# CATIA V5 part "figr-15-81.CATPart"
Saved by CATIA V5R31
Part number: Part1
Bounding box of the stored display mesh (mm): x -28.659 to 28.659, y -52 to 52, z 0 to 2
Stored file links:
  D:\PROJECTS\Project 2021\US EDITION\CATIA V5 6R 2021\Resources\Part Files\c15_catia_v5_6r2021_prt\figr-15-81.CATPart
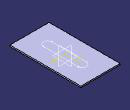
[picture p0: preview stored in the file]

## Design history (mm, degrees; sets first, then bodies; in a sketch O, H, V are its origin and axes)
SheetMetalParameters1: Thickness 2, BendRadius 4, KFactor 0.400515 {= log(min(100,max(20*SheetMetalParameters1.BendRadius,SheetMetalParameters1.Thickness)/SheetMetalParameters1.Thickness))/log(100)/2}, ReliefRadialLength 1, ReliefAxialLength 2, MinimumBendRadius 0
Body1 (main body)
  Sketch1 on xy-plane, origin (0, 0, 0), H (1, 0, 0), V (0, 1, 0)
    line L1 (28.6588, 52) -> (28.6588, -52)
    line L2 (28.6588, -52) -> (-28.6588, -52)
    line L3 (-28.6588, -52) -> (-28.6588, 52)
    line L4 (-28.6588, 52) -> (28.6588, 52)
    vertical: L1 V, L3 V
    horizontal: L2 H, L4 H
    equidistance: L1 L3 O, L2 L4 O
  Wall1: Thickness 2, Profile Sketch1, OffsetValue 0
  Sketch2 on face of Wall1, origin (0, 0, 2), H (1, 0, 0), V (0, 1, 0)
    construction line L1 (0, 25.3065) -> (0, -25.5921)
    point P1 (0, 25.3065)
    line L2 (6, 25.3065) -> (6, -25.5921)
    line L3 (-6, -25.5921) -> (-6, 25.3065)
    arc A1 centre (0, -25.5921) radius 6 from (6, -25.5921) to (-6, -25.5921) cw
    arc A2 centre (0, 25.3065) radius 6 from (-6, 25.3065) to (6, 25.3065) cw
    distance L1 L2 = 6
    coincidence: P1 V
    vertical: L1 V
    tangency: A1 L2, A2 L2, A1 L3, A2 L3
